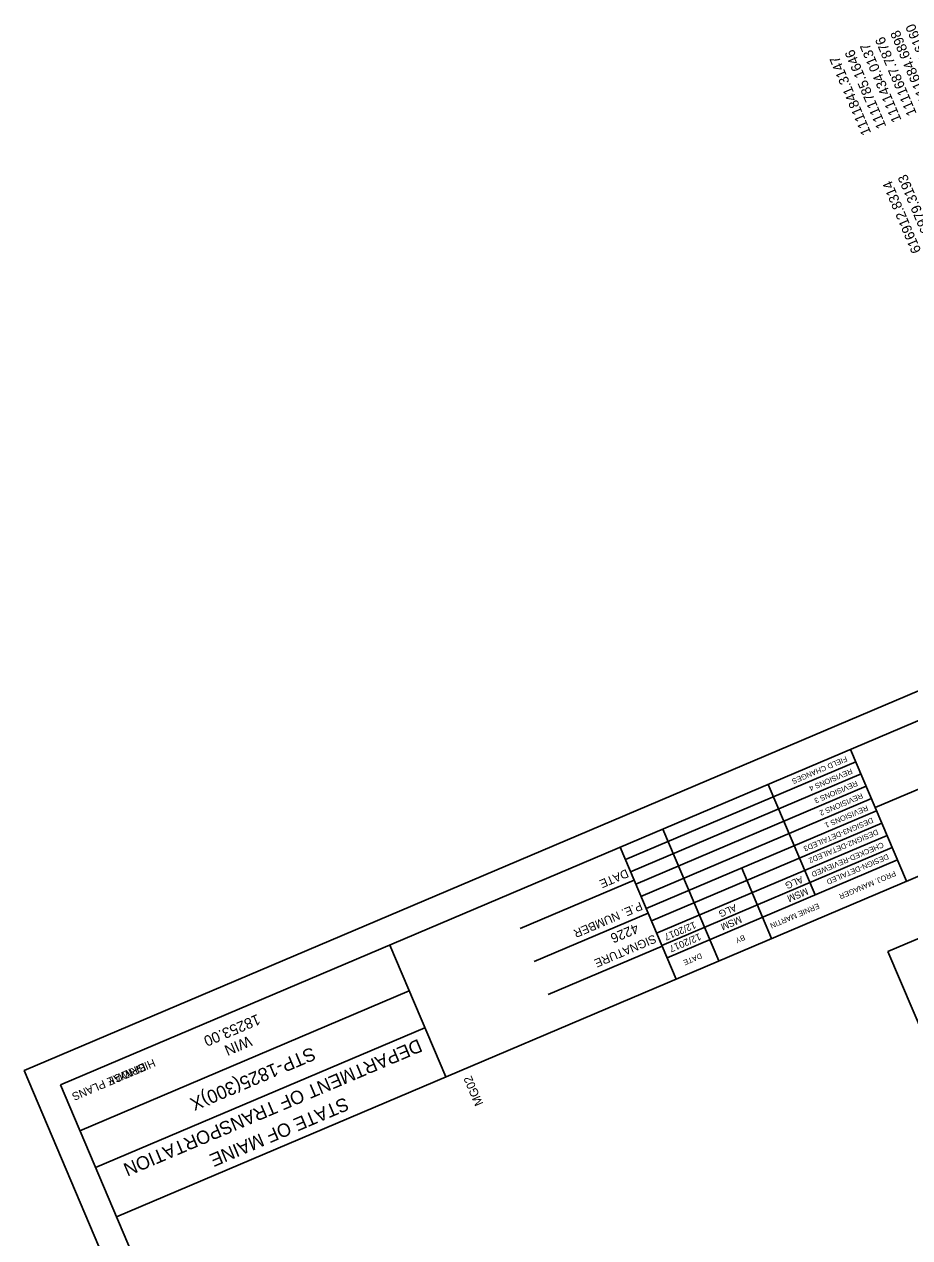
# Model space of a CAD drawing. Extents: x 1111260 to 1112147, y 617053 to 618212.
# Drawn here: x 1111259.6 to 1111569, y 617777.2 to 618201.1 of the extents above; entities that cross this region are included whole.
import ezdxf

# ---------------------------------------------------------------- set-up
doc = ezdxf.new("R2010")
doc.units = 0
for name, color, linetype in [('ANNOTATION', 7, 'Continuous'), ('BORDER', 7, 'Continuous'), ('BRIDGE_TITLE', 7, 'Continuous'), ('D_Roadway_Centerline_Text', 7, 'Continuous'), ('H_V CONTROLS', 7, 'Continuous'), ('HIGHWAY_TITLE', 7, 'Continuous'), ('PLOT BOUNDARY', 7, 'Continuous')]:
    doc.layers.add(name, color=color, linetype=linetype)

msp = doc.modelspace()

# ---------------------------------------------------------------- linework, layer by layer
at = {"layer": 'BORDER'}
for p, q in [((1111755.5, 618035.73), (1111272.23, 617830.6)), ((1111718.09, 617995.9), (1111557, 617927.52)), ((1111775.03, 617989.7), (1111291.77, 617784.57)), ((1111567.92, 617901.79), (1111548.38, 617947.82)), ((1111487.38, 617867.6), (1111467.84, 617913.63)), ((1111472.72, 617902.12), (1111432.92, 617885.23)), ((1111477.61, 617890.61), (1111437.81, 617873.72)), ((1111406.87, 617833.43), (1111387.34, 617879.45)), ((1111482.49, 617879.11), (1111442.69, 617862.21)), ((1111394.12, 617863.45), (1111279.05, 617814.61)), ((1111399.58, 617850.58), (1111284.51, 617801.74)), ((1111272.25, 617830.6), (1111584.83, 617094.2))]:
    msp.add_line(p, q, dxfattribs=at)
for points in [[(1111550.19, 617943.53), (1111469.66, 617909.34)], [(1111552.01, 617939.24), (1111471.48, 617905.05)], [(1111553.83, 617934.95), (1111473.3, 617900.77)], [(1111536, 617897.01), (1111519.62, 617935.6)], [(1111555.65, 617930.66), (1111475.12, 617896.48)], [(1111557.47, 617926.37), (1111476.94, 617892.19)], [(1111559.29, 617922.09), (1111478.76, 617887.9)], [(1111502.34, 617873.95), (1111482.8, 617919.98)], [(1111480.58, 617883.61), (1111561.11, 617917.8)], [(1111562.93, 617913.51), (1111482.4, 617879.33)], [(1111564.75, 617909.22), (1111484.22, 617875.04)], [(1111517.59, 617889.2), (1111510.31, 617906.35)], [(1111520.75, 617881.77), (1111517.59, 617889.2)]]:
    msp.add_lwpolyline(points, dxfattribs=at)
at = {"layer": 'H_V CONTROLS'}
for p, q in [((1111561.42, 617877.19), (1111625.85, 617904.55)), ((1111644.45, 617681.59), (1111561.42, 617877.19))]:
    msp.add_line(p, q, dxfattribs=at)
at = {"layer": 'PLOT BOUNDARY'}
msp.add_lwpolyline([(1112097.99, 617268.06), (1111765.87, 618050.49), (1111259.59, 617835.59), (1111591.71, 617053.16)], close=True, dxfattribs=at)

# ---------------------------------------------------------------- texts
at = {"layer": 'ANNOTATION'}
for s, height, rotation, p in [('1111684.6898', 3.45, 113, (1111576.82, 618172.23)), ('1111674.6160', 3.45, 113, (1111582.12, 618174.49)), ('1111687.7876', 3.45, 113, (1111571.51, 618169.98)), ('1111785.1646', 3.45, 113, (1111560.9, 618165.48)), ('1111434.0137', 3.45, 113, (1111566.21, 618167.73)), ('1111841.3147', 3.45, 113, (1111555.6, 618163.23)), ('616979.3193', 3.45, 113, (1111578.41, 618124.23)), ('616912.8314', 3.45, 113, (1111573.11, 618121.98)), ('4226', 3.396, 203, (1111473.4, 617887.09))]:
    msp.add_text(s, height=height, rotation=rotation, dxfattribs=at).set_placement(p)
at = {"layer": 'BORDER'}
for s, height, p in [('FIELD CHANGES', 1.8637, (1111546.72, 617945.49)), ('REVISIONS 4', 1.8637, (1111548.54, 617941.21)), ('REVISIONS 3', 1.8637, (1111550.36, 617936.92)), ('REVISIONS 2', 1.8637, (1111552.18, 617932.63)), ('REVISIONS 1', 1.8637, (1111554, 617928.34)), ('DESIGN3-DETAILED3', 1.8637, (1111555.82, 617924.05)), ('DESIGN2-DETAILED2', 1.8637, (1111557.57, 617919.94)), ('CHECKED-REVIEWED', 1.8637, (1111559.46, 617915.48)), ('DESIGN-DETAILED', 1.8637, (1111561.21, 617911.36)), ('DATE', 2.953, (1111470, 617906.08)), ('ALG', 2.423, (1111531.15, 617903.66)), ('PROJ. MANAGER', 1.8637, (1111563.71, 617905.46)), ('MSM', 2.423, (1111532.9, 617899.54)), ('P.E. NUMBER', 2.9528, (1111474.85, 617894.66)), ('ALG', 2.423, (1111507.94, 617893.81)), ('ERNIE MARTIN', 1.8637, (1111537, 617894.12)), ('MSM', 2.423, (1111509.69, 617889.69)), ('12/2017', 2.423, (1111493.75, 617887.78)), ('SIGNATURE', 2.953, (1111479.69, 617883.24)), ('12/2017', 2.423, (1111495.5, 617883.67)), ('BY', 1.857, (1111511.03, 617883.1)), ('DATE', 1.857, (1111495.97, 617876.71)), ('18253.00', 3.726, (1111341.08, 617855.45)), ('WIN', 3.726, (1111338.08, 617847.88)), ('DEPARTMENT OF TRANSPORTATION', 4.6588, (1111397.33, 617846.8)), ('STP-1825(300)X', 4.6588, (1111360.15, 617843.97)), ('STATE OF MAINE', 4.6588, (1111371.73, 617826.42))]:
    msp.add_text(s, height=height, rotation=203, dxfattribs=at).set_placement(p)
at = {"layer": 'BRIDGE_TITLE'}
msp.add_text('BRIDGE PLANS', height=2.795, rotation=203, dxfattribs=at).set_placement((1111301.4, 617838.4))
at = {"layer": 'D_Roadway_Centerline_Text'}
msp.add_text('MG02', height=3, rotation=113.0652, dxfattribs=at).set_placement((1111420.04, 617824.05))
at = {"layer": 'HIGHWAY_TITLE'}
msp.add_text('HIGHWAY PLANS', height=2.795, rotation=203, dxfattribs=at).set_placement((1111304.66, 617839.79))

doc.saveas('drawing.dxf')
